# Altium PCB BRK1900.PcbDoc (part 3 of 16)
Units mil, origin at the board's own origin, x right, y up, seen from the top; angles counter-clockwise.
Board outline 8858.27 x 5905.51 mil, 10 copper layers (L1-TOP, L2-GND, L3-PWR, L4-GND, L5-PWR, L6-PWR, L7-GND, L8-SIG, L9-GND, L10-BOT), stack 48.824 mil thick; 456 components, 571 nets, 2296 pads, 2416 vias.
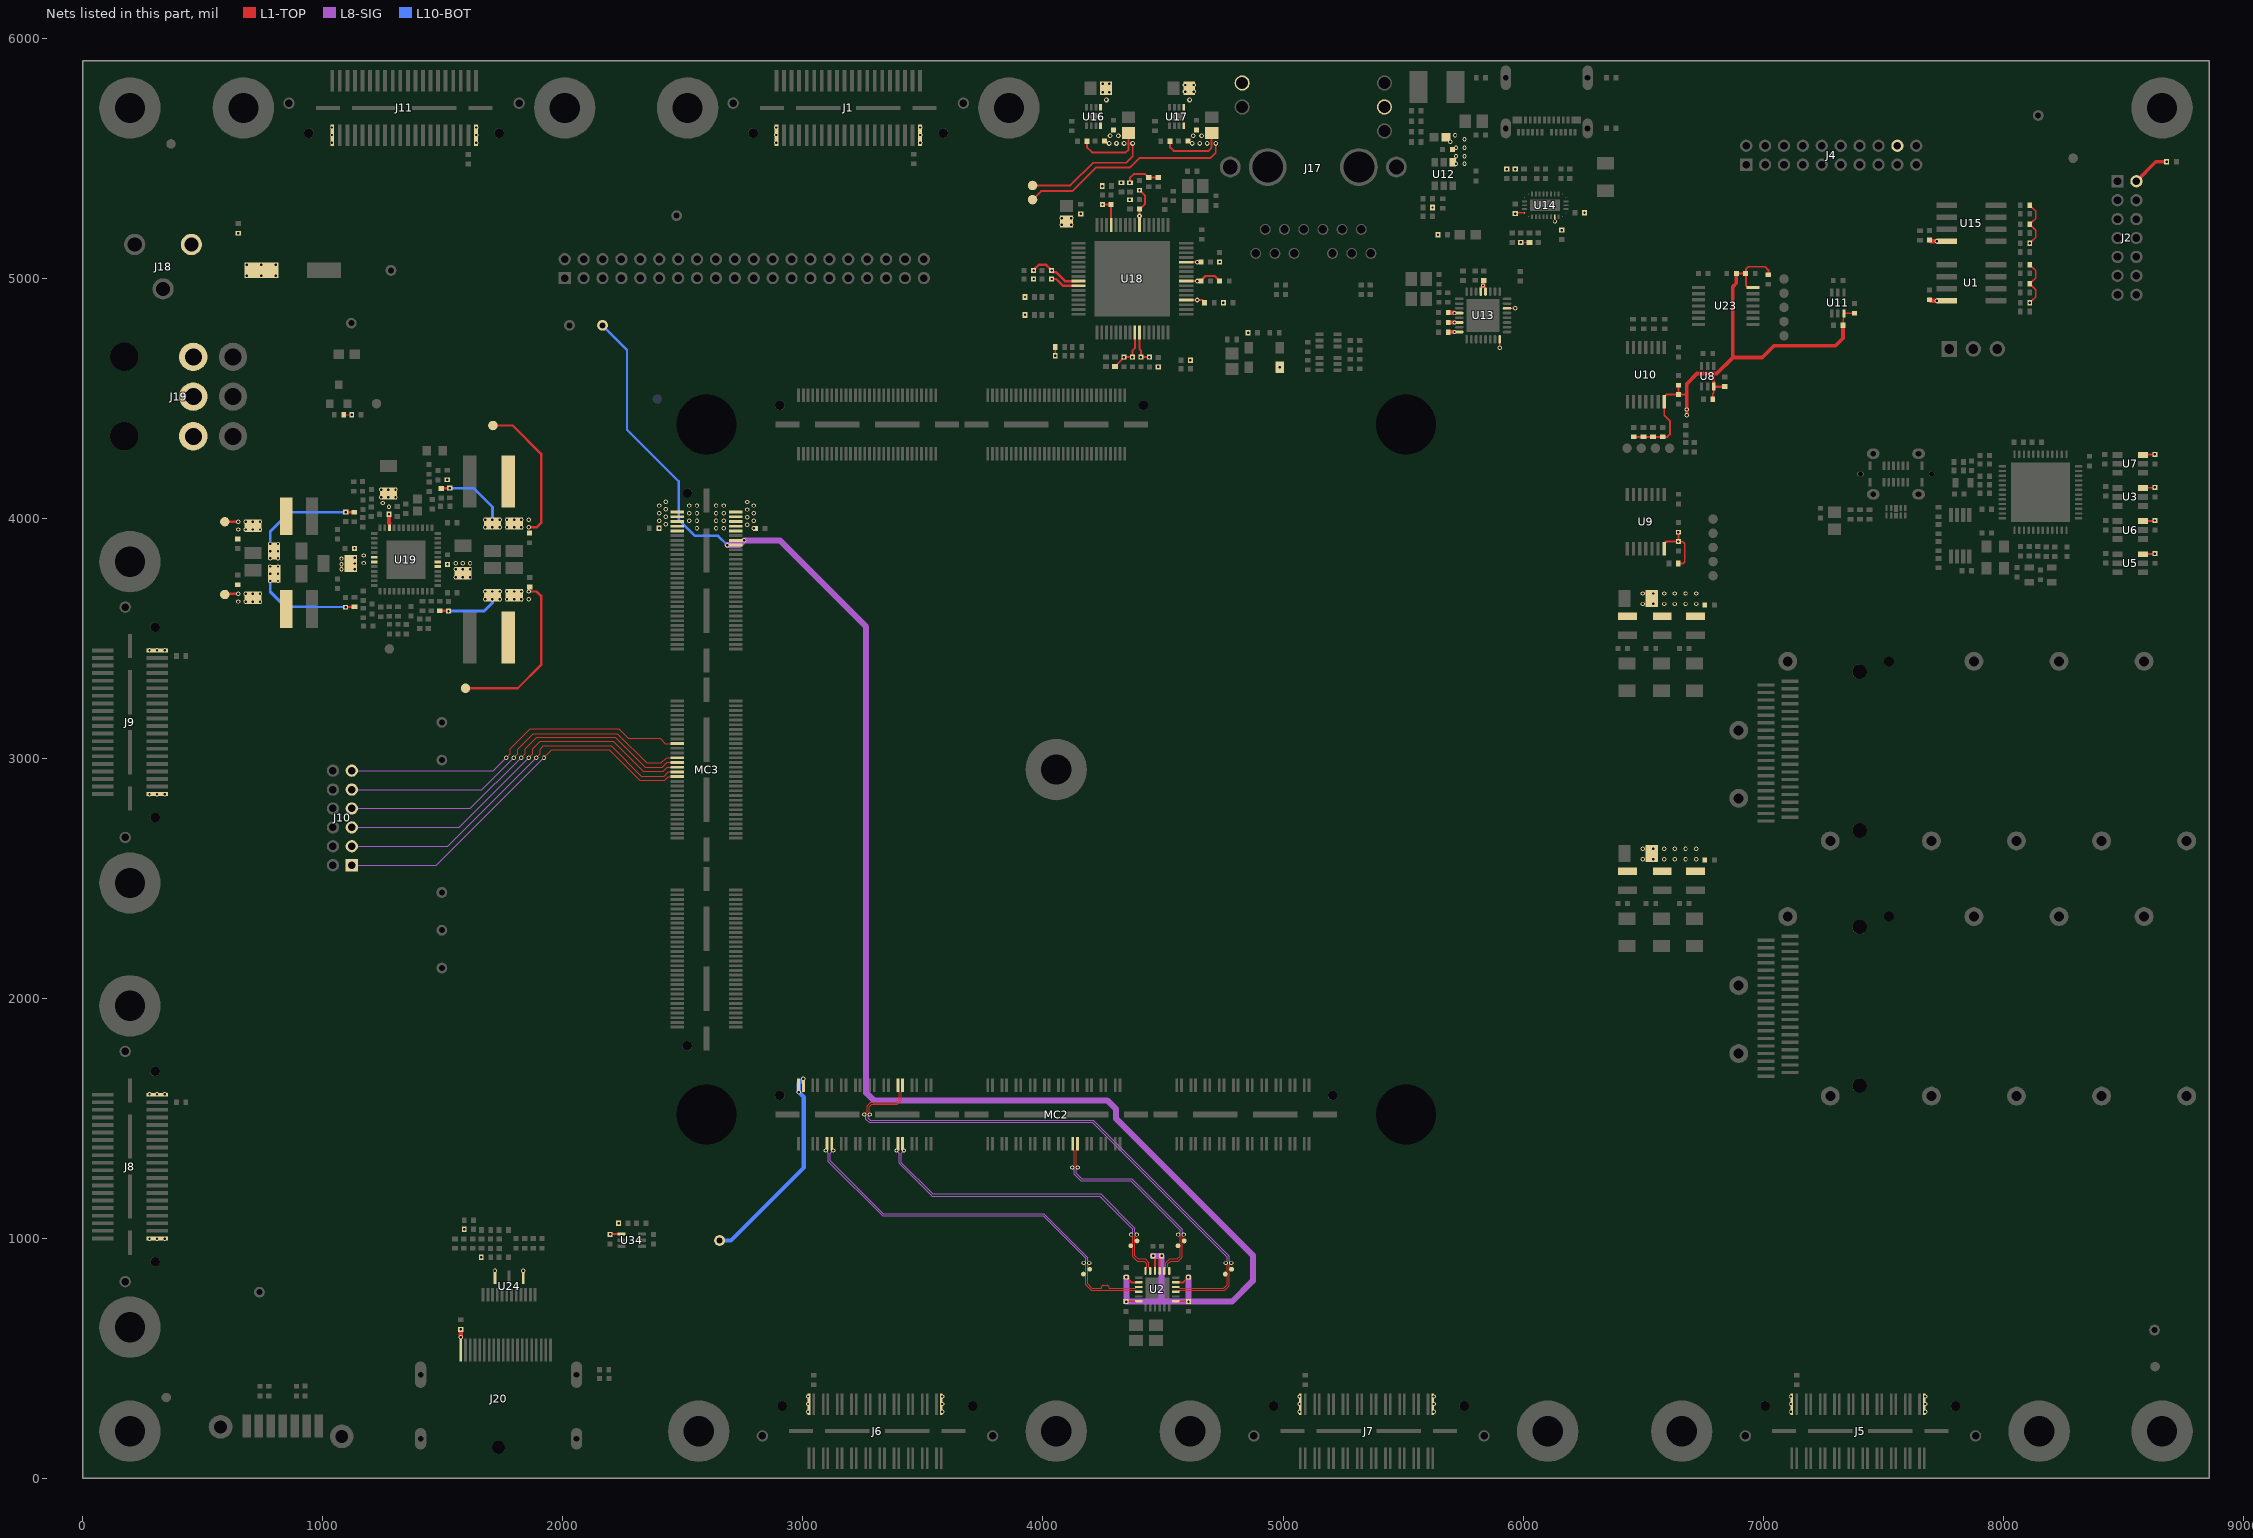
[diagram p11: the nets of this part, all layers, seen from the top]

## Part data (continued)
R2 R3 R4 R5 R6 R7 R68 R74 R80 R81 R83 R84 R85 R86 R87 R88 R89: library part 001521, "Thick-film resistor", Manufacturer=Vishay, ValueFloat=10000, x_tolerance=1
R8: library part 002203, "Thick-film resistor", Manufacturer=Yageo, Tolerance (%)=1, ValueFloat=14300
R9 R11 R21 R28 R103 R104 R106 R112 R120 R121 R140 R148: library part 001521, "Thick-film resistor", Manufacturer=Vishay, Tolerance (%)=1, ValueFloat=10000
R10: library part 001713, Manufacturer=Vishay, Manufacturer_PN=CRCW04020000Z0EDC, ValueFloat=0, x_tolerance=1
R12 R154 R159 R167: library part 001070, Manufacturer=Vishay, ValueFloat=100000, x_tolerance=1
R13 R19: library part 001919, "Thick-film resistor", Manufacturer=Vishay, Tolerance (%)=1, ValueFloat=5100
R14: library part 000934, Manufacturer=Vishay, ValueFloat=24900, x_tolerance=1
R15: library part 001783, Manufacturer=Vishay, ValueFloat=18700, x_tolerance=1
R16: library part 001549, "Thick-film resistor", Manufacturer=Vishay, ValueFloat=210000, x_tolerance=1
R17: library part 001550, "Thick-film resistor", Manufacturer=Vishay, ValueFloat=84500, x_tolerance=1
R18: library part 001035, Manufacturer=Vishay, ValueFloat=49900, x_tolerance=1
R20: library part 000826, "Thick-film resistor", Manufacturer=Vishay, Tolerance (%)=1, ValueFloat=12000
R22 R23 R24 R93 R108 R109 R110 R111: library part 000755, "Thick-film resistor", Manufacturer=Vishay, Tolerance (%)=1, ValueFloat=0
R25 R26: library part 001070, "Thick-film resistor", Manufacturer=Vishay, Tolerance (%)=1, ValueFloat=100000
R27 R138: library part 001162, "Thick-film resistor", Manufacturer=Vishay, Tolerance (%)=1, ValueFloat=2000
R41 R42 R43 R44 R45 R46 R47 R48 R49 R50 R51 R52 R97 R99 R100 R101: library part 001008, Manufacturer=Vishay, ValueFloat=4750, x_tolerance=1
R58: library part 000932, "Thick-film resistor", Manufacturer=Vishay, Tolerance (%)=1, ValueFloat=226000
R59: library part 001281, "Thick-film resistor", Manufacturer=Vishay, Tolerance (%)=1, ValueFloat=270000
R60 R134: library part 001618, "Thick-film resistor", Manufacturer=Vishay, Tolerance (%)=1, ValueFloat=374000
R61: library part 000967, "Thick-film resistor", Manufacturer=Vishay, Tolerance (%)=1, ValueFloat=118000
R62 R63 R64 R92: library part 002438, "NoLoad resistor", Manufacturer=Generic, Manufacturer_PN=Resistor-NoLoad
R65: library part 001162, Manufacturer=Vishay, ValueFloat=2000, x_tolerance=1
R66: library part 001121, Manufacturer=Vishay, ValueFloat=15000, x_tolerance=1
R67 R70 R73 R77 R78 R79 R119: library part 000755, "Thick-film resistor", Manufacturer=Vishay, ValueFloat=0, x_tolerance=1
R69: library part 000797, "Thick-film resistor", Manufacturer=Vishay, ValueFloat=1000, x_tolerance=1
R71: library part 001945, Manufacturer=Vishay, ValueFloat=499000, x_tolerance=1
R72: library part 001853, Manufacturer=Vishay, ValueFloat=887000, x_tolerance=1
R75 R117: library part 000800, "Thick-film resistor", Manufacturer=Vishay, ValueFloat=1000000, x_tolerance=5
R76: library part 001266, "Thick-film resistor", Manufacturer=Vishay, ValueFloat=8060, x_tolerance=1
R82: library part 001549, Manufacturer=Vishay, ValueFloat=210000, x_tolerance=1
R90 R91 R113 R114 R115 R116: library part 000801, "Thick-film resistor", Manufacturer=Vishay, Tolerance (%)=5, ValueFloat=2200
R94 R98 R102: library part 000760, "Thick-film resistor", Manufacturer=Vishay, ValueFloat=240, x_tolerance=1
R95: library part 002155, "Thick-film resistor", Manufacturer=Vishay, Tolerance (%)=1, ValueFloat=5760
R96 R105 R183 R184: library part 001388, "Thick-film resistor", Manufacturer=Vishay, Tolerance (%)=1, ValueFloat=2490
R107: library part 000800, "Thick-film resistor", Manufacturer=Vishay, Tolerance (%)=5, ValueFloat=1000000
R118: library part 001840, "Thick-film resistor", Manufacturer=Vishay, Tolerance (%)=1, ValueFloat=11000
R122 R125: library part 001091, Manufacturer=Vishay, Manufacturer_PN=CRCW040231K6FKED, ValueFloat=31600, x_tolerance=1
R123 R126 R130 R135: library part 001521, Manufacturer=Vishay, Manufacturer_PN=CRCW040210K0FKED, ValueFloat=10000, x_tolerance=1
R124 R127 R129 R133: library part 001121, "Thick-film resistor", Manufacturer=Vishay, Tolerance (%)=1, ValueFloat=15000
R128 R132: library part 001157, Manufacturer=Vishay, ValueFloat=52300, x_tolerance=1
R131: library part 001521, Manufacturer=Vishay, ValueFloat=10000, x_tolerance=1
R136: library part 000411, Manufacturer=Vishay, ValueFloat=0
R137: library part 000759, Manufacturer=Vishay, ValueFloat=10000, x_tolerance=5
R151 R152: library part 000755, Manufacturer=Vishay, ValueFloat=0, x_tolerance=1
R153 R158: library part 001715, Manufacturer=Vishay, ValueFloat=49.9, x_tolerance=1
R155 R156 R157: library part 001850, Manufacturer=Vishay, ValueFloat=1000000, x_tolerance=5
R168: library part 001388, Manufacturer=Vishay, ValueFloat=2490, x_tolerance=1
R169: library part 002012, Manufacturer=Vishay, ValueFloat=1500, x_tolerance=1
R181: library part 000969, Manufacturer=Vishay, ValueFloat=10, x_tolerance=1
TP1 TP2 TP3 TP4 TP5 TP6 TP7 TP8 TP9 TP10 TP11 TP12 TP13 TP14: library part TP-PTH-25/45, "Test point, plated through-hole, 25/45mil", partnumber=ALIGNI_IGNORE
TP15 TP16 TP17 TP18 TP22 TP23 TP32 TP33 TP34 TP35 TP36 TP37 TP38 TP39 TP40 TP41 TP42 TP43 TP44 TP45 TP46: library part TESTPOINT-SMD40, "Test point, surface-mount, 40mil"
TP19: "Test point, surface-mount, 40mil"
TP24 TP25 TP26 TP27 TP28 TP29 TP30 TP31: "Test point, surface-mount, 20mil", partnumber=ALIGNI_IGNORE
U1: library part 000842, "EEPROM", Manufacturer=Microchip
U2: library part 001741, Manufacturer="Silicon Labs"
U3 U5 U6 U7: library part 002400, "Level Translator, 0.65V - 3.6V, Direction Control", Manufacturer="Texas Instruments"
U4: library part 002398, Manufacturer=FTDI
U8 U11 U34: library part 002140, "Level Translator, 0.65V - 3.6V, Direction Control", Manufacturer="Texas Instruments"
U9 U10 U23: library part 000178, Manufacturer=Maxim
U12: library part 002224, "Load Switch with Adjustable Current Limit, Latching", Manufacturer="Diodes Incorporated"
U13: library part 001262, "Hi-Speed USB PHY with ULPI interface", Manufacturer=Microchip
U14: library part 001944, Manufacturer="Texas Instruments"
U15: library part 001296, "2 kb I2C EEPROM, 400 kHz", Manufacturer=Microchip
U16 U17: library part 002102, "LDO, 500 mA, 1.7-5.5V input, 0.6-5.3V output, 1% accuracy", Manufacturer=Maxim
U18: library part 002091, "Gigabit ethernet transceiver, RGMII", Manufacturer="Texas Instruments"
U19: library part 001511, Manufacturer="Texas Instruments"
U20: library part 002441, Manufacturer="Opal Kelly Incorporated"
U24: library part 001946, Manufacturer="Texas Instruments"
Y1: library part 001531, "Crystal", Manufacturer=Abracon
Y2: library part 001742, Manufacturer=Epson
Y3: library part 000770, "Crystal", Manufacturer="MMD Monitor / Quartztek"
Y4: library part 002402, "Crystal", Manufacturer=Abracon

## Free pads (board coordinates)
  round 18 hole 10 mask+2: ViaNoConnect1(1095,3628.92) ViaNoConnect1(1096.2,4025.16) ViaNoConnect1(1523.58,3612.56) ViaNoConnect1(1529,4125.08)

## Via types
v1: diameter 18, hole 10, L1-TOP to L10-BOT, tented both sides, 2170 vias
v2: diameter 20, hole 10, L1-TOP to L10-BOT, tented both sides, 246 vias

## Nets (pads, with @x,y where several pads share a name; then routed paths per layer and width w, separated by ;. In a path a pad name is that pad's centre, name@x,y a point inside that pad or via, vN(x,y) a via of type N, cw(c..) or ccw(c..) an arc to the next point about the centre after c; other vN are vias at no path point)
+1.1V_ETH: C83.2 C84.2 C85.2 C90.2 C91.2 C92.2 C93.2 C95.2 C96.2 C97.2 C98.2 R58.2 TP22.1 U16.8 U18.8 U18.29 U18.42 U18.58 | length 1330.2
  L1-TOP w8: TP22.1@3956.69,5385.83 4114.17,5385.83 4208.66,5480.31 4346.46,5480.31 4374.02,5507.87 4374.02,5560.48 v2(4373.26,5561.23) ; R58.2@4183.3,5570.09 4183.3,5544.5 4204.57,5523.23 4344.31,5523.23 4356.3,5535.22 C85.2@4356.3,5604.92 ; C95.2@4283.46,5306.69 4283.46,5222.29 U18.29@4284.06,5221.69 ; U18.58@4402.17,4772.87 4402.17,4703.97 4408.08,4698.07 C91.2@4408.08,4670.9 C90.2@4443.51,4670.9 ; U18.8@4597.06,4987.44 v2(4642.33,4987.44)
  L1-TOP w10: C93.2@4035.83,4995.47 v1(4035.83,4996.06) 4055.12,4996.06 4083.43,4967.75 U18.42@4148.24,4967.75 ; v2(4248.03,5306.69) C95.2@4283.46,5306.69 ; C98.2@4657.48,4988.19 4657.48,4988.78 4677.47,5008.77 4715.84,5008.77 4735.83,4988.78 C97.2@4735.83,4988.19
  other v1: 3961.02,4996.06
  other v2: 4408.08,4670.51 4443.51,4670.51 4275.59,5561.23 4306.33,5561.23 4337.83,5561.23 4279.53,5592.72 4314.21,5592.72
+1.8V: C1.2 C12.2 C30.2 C34.2 C40.2 C71.2 C72.2 C74.2 C99.2 C100.2 C101.2 C102.2 C105.2 C106.2 C109.2 C110.2 D2.2 J2.2 J4.18 MC2.1 MC2.3 R62.2 R63.2 R64.2 R68.2 R95.2 R97.1 R99.2 R100.2 R101.2 R104.2 R113.2 R114.2 R115.2 R116.2 R183.2 TP1.1 U3.6 U5.6 U6.6 U7.6 U13.8 U13.14 U13.28 U13.30 U13.32 U18.23 U18.41 U18.57 | length 2163.1
  L1-TOP w7: U13.8@5902.45,4745.06 5902.45,4709.84 v1(5903.02,4709.28) ; U13.14@5932.96,4873.99 5966.73,4873.99 v1(5967.02,4874.28)
  L1-TOP w8: v1(4051.18,4677.17) R64.2@4051.18,4712.6 ; R95.2@4299.83,4631.6 4301.8,4631.6 4307.64,4637.44 4307.64,4639.83 4330.39,4662.58 4330.39,4664.66 4336.62,4670.9 v2(4337.21,4670.9) v1(4372.65,4670.9) 4372.65,4698.07 4382.49,4707.91 U18.57@4382.49,4772.87 ; v1(4362.2,5397.64) 4362.2,5417.32 4377.95,5433.07 4425.2,5433.07 4438.98,5419.29 R115.2@4440.94,5419.29 R116.2@4480.31,5419.29 ; C109.2@4401.57,5365.75 v1(4402.17,5365.75) 4425.2,5342.72 4425.2,5310.04 4402.17,5287.01 C110.2@4401.57,5287.01 4401.86,5286.72 4401.86,5258.83 v2(4402.14,5258.55) U18.23@4402.17,5221.69 ; U5.6@8582.3,3850.02 8583.48,3851.2 8630.33,3851.2 v2(8631.51,3852.38) ; U6.6@8582.3,3987.81 8583.48,3988.99 8630.33,3988.99 v2(8631.51,3990.17) ; U3.6@8582.3,4125.61 8583.48,4126.79 8630.33,4126.79 v2(8631.51,4127.97) ; U7.6@8582.3,4263.4 8583.48,4264.58 8630.33,4264.58 v2(8631.51,4265.76)
  L1-TOP w10: v1(3961.02,5031.5) 3967.26,5037.73 3967.26,5039.85 3982.53,5055.12 4013.53,5055.12 4029.59,5039.06 4029.59,5037.73 v1(4035.83,5031.5) 4035.83,5030.91 4042.06,5024.67 4053.92,5024.67 4091.15,4987.44 U18.41@4148.24,4987.44
  L1-TOP w15: J2.2@8554.76,5403.22 8635.79,5484.25 v1(8680.71,5484.25)
  L1-TOP w18: C74.2@5688.09,4774.28 C74.2@5688.09,4774.28 5689.33,4775.57 v1(5714.14,4775.57) ; C72.2@5688.09,4815.28 5688.43,4814.94 v1(5714.14,4814.94) ; C71.2@5688.09,4856.28 5712.17,4856.28 v1(5714.14,4854.31)
  L1-TOP w25: C99.2@4095.7,5223.13 4098.43,5225.85 C99.2@4098.43,5235.24
  L10-BOT w18: TP1.1@2653,991 2700,991 3004,1295 3004,1587.68 v1(2982.28,1609.4) 2982.28,1645.72 v1(3001.97,1665.4)
  other v1: 4985.77,4628.25 4480.31,4629.92 4614.17,4657.48 4854.33,4771.65 3925.2,4846.46 3925.2,4921.26 4157.48,5267.32 5622.69,5294 4362.2,5326.77 4246.34,5383.29 4326.77,5397.64
  other v2: 4078.74,5222.44 4118.11,5222.44 4078.74,5250 4118.11,5250
+2.5V_ETH: C87.2 C88.2 C89.2 C103.2 C104.2 C107.2 C108.2 R60.2 TP46.1 U17.8 U18.4 U18.12 | length 1281.7
  L1-TOP w8: TP46.1@3956.69,5326.77 3992.13,5362.2 4122.05,5362.2 4220.35,5460.51 4362.08,5460.51 4401.57,5500 4696.85,5500 4719.72,5522.87 v2(4719.72,5561.23) ; R60.2@4529.53,5570.47 4529.53,5544.27 4543.91,5529.89 4689.58,5529.89 4702.76,5543.07 C89.2@4702.76,5604.92 ; U18.4@4597.06,4908.7 v2(4642.33,4908.7) ; U18.12@4597.06,5066.18 v2(4642.33,5066.18)
  L1-TOP w10: v2(4642.33,4908.7) 4662.17,4908.7 4667.4,4903.46 4667.99,4903.46 4673.23,4898.23 C103.2@4673.23,4897.64
  other v1: 4751.57,4897.64 4735.83,5066.93
  other v2: 4622.05,5561.23 4652.79,5561.23 4684.29,5561.23 4625.98,5592.72 4660.66,5592.72
+3.3V: C3.2 C4.2 C5.2 C6.2 C7.2 C8.2 MC3.166 MC3.168 TP3.1 U2.7 U2.11 U2.15 U2.16 U2.20 U2.24 | length 7320.6
  L1-TOP w8: C4.2@4346.46,736.61 4348.03,738.19 U2.24@4399.61,738.19 ; C3.2@4346.46,838.19 v1(4347.05,838.19) 4368.31,816.93 U2.20@4399.61,816.93 ; v1(4458.74,926.83) 4459.34,926.83 4466.54,919.63 U2.16@4466.54,864.17 ; U2.15@4486.22,864.17 4486.22,919.47 4493.59,926.83 v1(4494.18,926.83) ; U2.7@4553.15,738.19 4604.72,738.19 C8.2@4606.3,736.61 ; U2.11@4553.15,816.93 4584.45,816.93 v1(4605.71,838.19) C7.2@4606.3,838.19
  L8-SIG w25: v1(2685.08,3887.8) 2735.39,3887.8 v1(2755.08,3907.48) 2903.54,3907.48 3263.78,3547.24 3263.78,1606.3 3295.28,1574.8 4267.72,1574.8 4303.15,1539.37 4303.15,1500 4874.02,929.13 4874.02,822.83 4787.4,736.22 v1(4606.3,736.22) ; v1(4347.05,838.19) 4347.05,736.81 v1(4346.46,736.22) 4494.18,736.22 ; v1(4458.74,926.83) v1(4494.18,926.83) 4494.18,736.22 ; v1(4605.71,838.19) 4606.3,837.6 v1(4606.3,736.22) ; 4494.18,736.22 v1(4606.3,736.22)
  L10-BOT w10: TP3.1@2165.35,4803.15 2267.43,4701.07 2267.43,4368.57 2482.24,4153.76 2482.24,3993.76 2550,3926 2646.87,3926 v1(2685.08,3887.8) 2735.39,3887.8 v1(2755.08,3907.48)
+3.3V_AUX: C2.2 C73.2 C75.2 C82.2 C86.2 C94.2 C129.2 C130.2 C131.2 C133.2 C183.2 C218.2 J1.40 J5.40 J6.40 J7.40 J8.40 J9.40 J11.40 J17.14 J17.16 J20.20 L2.2 pad.ViaNoConnect1@1529,4125.08 R2.2 R3.2 R4.2 R65.2 R80.2 R82.2 R84.2 R85.2 R86.2 R125.2 R137.2 R138.2 R148.2 R151.1 R167.2 R168.2 TP16.1 U1.8 U13.20 U13.21 U14.8 U15.8 U16.1 U17.1 U24.13 U24.15 U34.1 | length 1695.3
  L1-TOP w5: R148.2@1087.69,4431 v1(1120.32,4431)
  L1-TOP w7: U14.8@6131.75,5256 6131.75,5236.75 v1(6132.55,5235.95) ; v1(8110.69,4897) 8110.69,4898.97 8117.03,4905.31 8119,4905.31 8134.97,4921.28 8134.97,4951.72 8119,4967.69 8117.03,4967.69 8110.69,4974.03 R3.2@8110.69,4976 8110.69,4977.97 8117.03,4984.31 8119,4984.31 8134.97,5000.28 8134.97,5031.72 8119,5047.69 8117.03,5047.69 8110.69,5054.03 R4.2@8110.69,5056 ; v1(8110.69,5145) 8110.69,5146.97 8117.03,5153.31 8119,5153.31 8134.97,5169.28 8134.97,5199.72 8119,5215.69 8117.03,5215.69 8110.69,5222.03 R85.2@8110.69,5224 8110.69,5225.97 8117.03,5232.31 8119,5232.31 8134.97,5248.28 8134.97,5279.72 8119,5295.69 8117.03,5295.69 8110.69,5302.03 R86.2@8110.69,5304
  L1-TOP w8: v1(2196.85,1016.54) 2197.64,1017.32 2243.31,1017.32 U34.1@2244.09,1018.11
  L1-TOP w9: C133.2@1528,4125.08 1527.3,4124.38 1494.7,4124.38 C133.2@1529,4125.08
  L1-TOP w10: TP16.1@1708.66,4385.83 1791.34,4385.83 1909.45,4267.72 1909.45,3980.32 1890.77,3961.64 v1(1857.58,3961.64) v1@1858.22,3961 ; U13.21@5823.71,4943.87 5823.9,4944.07 5823.9,4959.1 5833.02,4968.21 5843.2,4958.03 5843.2,4944.07 U13.20@5843.39,4943.87
  L1-TOP w12: v2(4276.81,5773.83) C82.2@4276.96,5773.83 ; C86.2@4592.13,5776.78 v2(4592.13,5776.93)
  L1-TOP w18: v1(1574.53,620.92) 1574.53,588.82 v1(1575.01,588.34) ; v1(5833.02,4969.28) 5834.19,4970.45 5834.19,4988.96 5835.43,4990.2 C73.2@5836.02,4990.2 ; C2.2@7693,4909.92 7693.59,4909.92 7697.51,4906 v1(7722.64,4906) U1.8@7764.64,4906 ; C94.2@7693,5157.92 7693.59,5157.92 7697.51,5154 v1(7722.64,5154) U15.8@7764.64,5154
  L10-BOT w12: pad.ViaNoConnect1@1529,4125.08 1629.32,4123.68 1706.58,4046.42 v1(1706.58,3993.81)
  other v1: 3580.33,278.35 5627.57,278.35 7674.82,278.35 3580.33,309.84 5627.57,309.84 7674.82,309.84 3580.33,341.34 5627.57,341.34 7674.82,341.34 1717.2,865.39 1835.31,865.39 1660.16,922 278.15,998.81 309.65,998.81 341.15,998.81 1588.84,1038 2232.28,1063.39 278.15,2849.21 309.65,2849.21 341.15,2849.21 1676.58,3961.64 1706.58,3961.64 1736.58,3961.64 1767.58,3961.64 1797.58,3961.64 1827.58,3961.64 1676.58,3993.81 1736.58,3993.81 1767.58,3993.81 1797.58,3993.81 1827.58,3993.81 1857.58,3993.81 1518,4160.32 5645.31,5180 6161.35,5200.08 6255.78,5272.32 5931.41,5454.01 1038.18,5564.37 2888.58,5564.37 1038.18,5595.86 2888.58,5595.86 1038.18,5627.36 2888.58,5627.36
  other v2: 4264.22,5742.32 4610.67,5742.32 4249.25,5773.83 4627.57,5776.93 4592.13,5804.49 4627.57,5804.49 4249.25,5809.26 4276.81,5809.26
+3.3V_QSFP: C50.2 C51.2 C52.2 C60.2 C61.2 C63.2 C64.2 C66.2 C67.2 C68.2 C119.2 C120.2 C121.2 C122.2 C212.2 C213.2 L1.2 L5.1 L6.1 L7.1 L8.1 L9.1 L10.1 pad.ViaNoConnect1@1523.58,3612.56 R41.2 R42.2 R43.2 R44.2 R45.2 R46.2 R51.2 R52.2 R122.2 TP15.1 U8.6 U9.14 U10.14 U11.6 U23.14 | length 3428.4
  L1-TOP w6: R41.2@6790.37,4495.95 6790.37,4518.43 6794.49,4522.54 U8.6@6794.49,4547.65 ; R51.2@7332.5,4803.67 7332.5,4828.14 7336.61,4832.26 U11.6@7336.61,4853.36
  L1-TOP w8: R46.2@6461.28,4338.68 R45.2@6501.28,4338.68 R44.2@6541.28,4338.68 R43.2@6581.28,4338.68 6601.28,4338.68 6611.28,4348.68 6611.28,4405.36 6588.05,4428.59 U10.14@6588.05,4484.81 ; U10.14@6587.43,4484.18 6587.43,4504.85 6596.91,4514.34 6646.59,4514.34 C64.2@6646.59,4552.92 ; U9.14@6587.78,3872.61 6587.78,3893.28 6597.27,3902.76 v1(6646.94,3902.76) ; R42.2@6646.65,3811.02 6665.35,3811.02 6673.23,3818.9 6673.23,3893.7 6665.35,3901.57 6648.13,3901.57 v1(6646.94,3902.76) ; v1(6646.94,3941.35) v1(6646.94,3902.76) ; C63.2@6647.22,4514.97 6681.1,4514.97 ; C213.2@6889.01,5019.06 C212.2@6927.59,5019.06 ; U23.14@6937.08,4959.89 6927.59,4969.38 C212.2@6927.59,5019.06 ; R52.2@7021.65,5013.78 7021.65,5033.46 7007.87,5047.24 6937.01,5047.24 6927.59,5037.83 C212.2@6927.59,5019.06 ; U11.6@7336.61,4853.36 7336.84,4853.59 C66.2@7380.02,4853.59
  L1-TOP w10: TP15.1@1594.49,3291.34 1812.23,3291.34 1909.45,3388.56 1909.45,3675.96 1890.77,3694.64 v1(1857.58,3694.64) v1@1858.22,3695.28 ; 6795.28,4602.36 6794.49,4601.57 U8.6@6794.49,4547.65 6794.72,4547.87 C50.2@6839.9,4547.87
  L1-TOP w11: R122.2@1487.58,3613.95 1522.19,3613.95 C122.2@1523.58,3612.56
  L1-TOP w15: v1(6681.1,4429.13) v1(6681.1,4452.76) 6681.1,4514.97 6681.1,4559.06 6724.41,4602.36 6795.28,4602.36 6807.09,4602.36 6874.02,4669.29 ; C213.2@6888.38,5019.68 6888.38,4978.93 6874.02,4964.57 6874.02,4669.29 ; R51.2@7332.5,4803.67 7332.5,4749.82 7300.91,4718.23 7045,4718.23 6996.06,4669.29 6874.02,4669.29
  L10-BOT w12: pad.ViaNoConnect1@1523.58,3612.56 1671.56,3612.56 1706.58,3647.58 v1(1706.58,3662.46)
  other v1: 6498.03,2579.72 6542.72,2579.72 6587.4,2579.72 6632.09,2579.72 6676.77,2579.72 6721.46,2579.72 6498.03,2623.03 6542.72,2623.03 6587.4,2623.03 6632.09,2623.03 6676.77,2623.03 6721.46,2623.03 6498.03,3642.72 6542.72,3642.72 6587.4,3642.72 6632.09,3642.72 6676.77,3642.72 6721.46,3642.72 1676.58,3662.46 1736.58,3662.46 1767.58,3662.46 1797.58,3662.46 1827.58,3662.46 1857.58,3662.46 6498.03,3686.02 6542.72,3686.02 6587.4,3686.02 6632.09,3686.02 6676.77,3686.02 6721.46,3686.02 1676.58,3694.64 1706.58,3694.64 1736.58,3694.64 1767.58,3694.64 1797.58,3694.64 1827.58,3694.64
+5V_AUX: C69.2 C76.2 C142.2 C143.2 C144.2 C145.2 C220.2 L3.2 pad.ViaNoConnect1@1096.2,4025.16 R71.2 R74.2 R81.2 R128.2 TP17.1 U12.1 U14.30 | length 602.2
  L1-TOP w5: v1(5990.41,5148.64) R74.2@6026.41,5148.64
  L1-TOP w7.5: v1(5967.41,5268.24) 5970.91,5271.75 U14.30@6005.76,5271.75
  L1-TOP w10: TP17.1@592,3985 648.39,3985 v1(648.58,3984.81) ; C145.2@1095.8,4025.55 pad.ViaNoConnect1@1096.2,4025.16 ; pad.ViaNoConnect1@1096.2,4025.16 1130.8,4025.16 pad.ViaNoConnect1@1096.2,4025.16
  L10-BOT w12: v1(781.19,3892.58) 781.19,3944.19 861.76,4024.76 pad.ViaNoConnect1@1096.2,4025.16
  other v1: 781.19,3832.58 813.36,3832.58 781.19,3862.58 813.36,3862.58 813.36,3892.58 648.58,3952.64 678.58,3952.64 708.58,3952.64 738.58,3952.64 678.58,3984.81 708.58,3984.81 738.58,3984.81 5967.41,5454.01 5720.47,5476.38 5755.91,5476.38 5720.47,5507.87 5755.91,5507.87 5720.47,5543.31 5755.91,5543.31 5696.85,5567.91 5755.91,5578.74 5716.54,5594.49
+5V_SZG: C150.2 C151.2 C152.2 C153.2 J1.2 J5.2 J6.2 J7.2 J8.2 J9.2 J11.2 L4.2 pad.ViaNoConnect1@1095,3628.92 R132.2 TP18.1 | length 521
  L1-TOP w10: TP18.1@585,3682 587.64,3684.64 v1(648.58,3684.64) ; C153.2@1095,3628.92 1130.8,3630.12 1096.2,3630.12 C153.2@1095,3628.92
  L10-BOT w12: v1(781.35,3738.42) 781.35,3693.65 843.69,3631.32 pad.ViaNoConnect1@1095,3628.92
  other v1: 3021.15,278.35 5068.39,278.35 7115.64,278.35 3021.15,309.84 5068.39,309.84 7115.64,309.84 3021.15,341.34 5068.39,341.34 7115.64,341.34 278.15,1599.71 309.65,1599.71 341.15,1599.71 278.15,3450.11 309.65,3450.11 341.15,3450.11 648.58,3652.46 678.58,3652.46 708.58,3652.46 738.58,3652.46 678.58,3684.64 708.58,3684.64 738.58,3684.64 813.53,3738.42 781.35,3768.42 813.53,3768.42 781.35,3798.42 813.53,3798.42 1639.08,5564.37 3489.48,5564.37 1639.08,5595.86 3489.48,5595.86 1639.08,5627.36 3489.48,5627.36
+VDCIN: C20.1 C21.1 C116.1 C117.1 C127.1 C128.1 C134.1 C135.2 C140.1 C141.1 J18.1 J19.1 J19.2 J19.3 MC3.171 MC3.172 MC3.173 MC3.174 MC3.175 MC3.176 MC3.177 MC3.178 MC3.179 MC3.180 U19.5 U19.6 U19.22 U19.30 U19.31 | length 38
  L1-TOP w18: v1(1276.08,4016) 1276.08,3980.14 1277.58,3978.64
  other v1: 1553.58,3754.46 1583.58,3754.46 1613.58,3754.46 1078.11,3786.64 1133.86,3787.4 1553.58,3786.64 1583.58,3786.64 1613.58,3786.64 1519.58,3807.56 1078.11,3808.64 1133.86,3811.02 1553.58,3811.7 1583.58,3811.7 1613.58,3811.7 1170.95,3812.84 1078.11,3831.64 1133.86,3834.65 1170.95,3844.33 1132.08,3874 2401.01,3957.97 2558.49,3957.97 2638.36,3957.97 2669.86,3957.97 2795.84,3957.97 2768.28,3972.73 2428.15,3974.41 2401.01,3989.46 2526.99,3989.46 2558.49,3989.46 2638.36,3989.46 2669.86,3989.46 2795.84,3989.46 2768.28,4004.23 2428.15,4005.91 2401.01,4020.96 2526.99,4020.96 2558.49,4020.96 2638.36,4020.96 2669.86,4020.96 2795.84,4020.96 2768.28,4035.72 2428.15,4037.4 1276,4047 2401.01,4052.46 2526.99,4052.46 2558.49,4052.46 2638.36,4052.46 2669.86,4052.46 2795.84,4052.46 1250,4063 2768.28,4067.22 2428.15,4068.9 1243,4086.83 1273,4086.83 1303,4086.83 1243,4119 1273,4119 1303,4119 684.09,5010 744.09,5010 804.09,5010 684.09,5056 744.09,5056 804.09,5056 648,5186.92
B68_L2N_N3: J10.7 MC3.93 | length 1549.3
  L1-TOP w4: v1(1826.77,3002.58) 1843.27,3019.08 1843.27,3038.62 1891.26,3086.61 2218.36,3086.61 2342.36,2962.61 2415.07,2962.61 2434.75,2982.28 MC3.93@2476.77,2982.28
  L8-SIG w4: J10.7@1121,2790.74 1614.93,2790.74 v1(1826.77,3002.58)
B68_L2P_N2: J10.5 MC3.91 | length 1575.9
  L1-TOP w4: v1(1858.27,3002.58) 1874.76,3019.08 1874.76,3039.58 1906.05,3070.87 2209.04,3070.87 2335.02,2944.88 2418.09,2944.88 2435.81,2962.6 MC3.91@2476.77,2962.6
  L8-SIG w4: J10.5@1121,2712 1567.68,2712 v1(1858.27,3002.58)
B68_L18N_N11: J10.3 MC3.89 | length 1599.5
  L1-TOP w4: v1(1889.76,3002.58) 1906.26,3019.08 1906.26,3038.07 1919.37,3051.18 2200.88,3051.18 2326.87,2925.2 2421.54,2925.2 2439.25,2942.91 MC3.89@2476.77,2942.91
  L8-SIG w4: J10.3@1121,2633.26 1520.44,2633.26 v1(1889.76,3002.58)
B68_L18P_N10: J10.1 MC3.87 | length 1613.2
  L1-TOP w4: v1(1921.26,3002.58) 1953.5,3034.83 2193.52,3034.83 2319.92,2908.43 2424.17,2908.43 2438.98,2923.23 MC3.87@2476.77,2923.23
  L8-SIG w4: J10.1@1121,2554.52 1473.19,2554.52 v1(1921.26,3002.58)
B68_T0U_N12: J10.9 MC3.95 | length 1522.2
  L1-TOP w4: v1(1795.28,3002.58) 1811.77,3019.08 1811.77,3036.93 1877.2,3102.36 2227.65,3102.36 2349.7,2980.32 2410.84,2980.32 2432.49,3001.97 MC3.95@2476.77,3001.97
  L8-SIG w4: J10.9@1121,2869.48 1662.17,2869.48 v1(1795.28,3002.58)
B68_T2U_N12: J10.11 MC3.101 | length 1464.4
  L1-TOP w4: v1(1763.78,3002.58) 1780.28,3019.08 1780.28,3038.45 1863.87,3122.05 2232.28,3122.05 2271.65,3082.68 2405.51,3082.68 2427.17,3061.02 MC3.101@2476.77,3061.02
  L8-SIG w4: J10.11@1121,2948.22 1709.42,2948.22 v1(1763.78,3002.58)
CLK0A: MC2.10 TP28.1 U2.22 | length 1640
  L1-TOP w3.3: v1(4170.17,897.64) 4170.17,895.35 4177.17,888.35 4177.17,806.17 4200.43,782.9 4383.58,782.9 4388.92,777.56 U2.22@4399.61,777.56
  L8-SIG w3.15: v1(3094.49,1366.09) 3105.74,1354.85 3105.74,1319.46 3331.83,1093.36 4000.21,1093.36 4177.17,916.41 4177.17,906.91 4170.17,899.91 v1(4170.17,897.64)
CLK0B: MC2.12 TP24.1 U2.21 | length 1640
  L1-TOP w3.3: v1(4193.17,897.64) 4193.17,895.35 4186.17,888.35 4186.17,809.9 4204.16,791.9 4220.47,791.9 4239.22,791.9 ccw(c4239.22,797.56) 4244.88,797.56 4244.88,798.56 cw(c4250.54,798.56) 4250.54,804.22 4267.52,804.22 cw(c4267.52,798.56) 4273.18,798.56 4273.18,797.56 ccw(c4278.84,797.56) 4278.84,791.9 4308.79,791.9 4383.58,791.9 4388.92,797.24 U2.21@4399.61,797.24
  L8-SIG w3.15: v1(3125.98,1366.09) 3114.74,1354.85 3114.74,1323.19 3335.56,1102.36 4003.94,1102.36 4186.17,920.13 4186.17,906.91 4193.17,899.91 v1(4193.17,897.64)
CLK1A: MC2.30 TP29.1 U2.18 | length 1368.1
  L1-TOP w3.3: v1(4367.02,1015.75) 4367.02,1013.46 4374.02,1006.46 4374.02,924.28 4392.78,905.51 4421.26,905.51 4432.51,894.26 4432.51,880.2 4427.17,874.86 U2.18@4427.17,864.17
  L8-SIG w3.15: v1(3389.76,1366.09) 3401.01,1354.85 3401.01,1312.26 3534.6,1178.68 3537.23,1176.04 4236.43,1176.04 4374.02,1038.45 4374.02,1025.02 4367.02,1018.02 v1(4367.02,1015.75)
CLK1B: MC2.32 TP25.1 U2.17 | length 1368.1
  L1-TOP w3.3: v1(4390.02,1015.75) 4390.02,1013.46 4383.02,1006.46 4383.02,928.01 4396.51,914.51 4424.99,914.51 4441.51,897.99 4441.51,880.2 4446.85,874.86 U2.17@4446.85,864.17
  L8-SIG w3.15: v1(3421.26,1366.09) 3410.01,1354.85 3410.01,1315.99 3540.96,1185.04 4240.16,1185.04 4383.02,1042.18 4383.02,1025.02 4390.02,1018.02 v1(4390.02,1015.75)
CLK2A: MC2.66 TP30.1 U2.14 | length 894.4
  L1-TOP w3.3: v1(4122.36,1295.28) 4122.36,1297.56 4129.36,1304.56 4129.36,1365.79 4124.02,1371.13 MC2.66@4124.02,1394.09 ; U2.14@4505.91,864.17 4505.91,874.86 4511.25,880.2 4511.25,897.43 4528.33,914.51 4560.18,914.51 4570.87,925.2 4570.87,1006.46 4563.87,1013.46 v1(4563.87,1015.75)
  L8-SIG w3.15: v1(4122.36,1295.28) 4122.36,1293.01 4129.36,1286.01 4129.36,1267.36 4157.69,1239.03 4366.35,1239.03 4570.87,1034.52 4570.87,1025.02 4563.87,1018.02 v1(4563.87,1015.75)
CLK2B: MC2.68 TP26.1 U2.13 | length 894.4
  L1-TOP w3.3: MC2.68@4143.7,1394.09 4143.7,1371.53 4138.36,1366.19 4138.36,1304.56 4145.36,1297.56 v1(4145.36,1295.28) ; U2.13@4525.59,864.17 4525.59,874.86 4520.25,880.2 4520.25,893.7 4532.06,905.51 4563.91,905.51 4579.87,921.47 4579.87,1006.46 4586.87,1013.46 v1(4586.87,1015.75)
  L8-SIG w3.15: v1(4145.36,1295.28) 4145.36,1293.01 4138.36,1286.01 4138.36,1271.09 4161.42,1248.03 4370.08,1248.03 4579.87,1038.24 4579.87,1025.02 4586.87,1018.02 v1(4586.87,1015.75)
CLK3A: MC2.29 TP31.1 U2.10 | length 2355.7
  L1-TOP w3.3: v1(3255.19,1515.94) 3255.19,1518.22 3267.29,1530.32 3267.29,1551.67 3282.55,1566.93 3389.76,1566.93 3401.01,1578.18 3401.01,1609.42 3395.67,1614.76 MC2.29@3395.67,1637.4 ; U2.10@4553.15,797.24 4563.84,797.24 4569.18,791.9 4752.53,791.9 4767.72,807.09 4767.72,888.35 4760.72,895.35 v1(4760.72,897.64)
  L8-SIG w3.15: v1(3255.19,1515.94) 3255.19,1513.67 3262.19,1506.67 3262.19,1497.19 3276.26,1483.13 4205.85,1483.13 4725.92,963.06 4732.28,956.69 4767.72,921.26 4767.72,906.91 4760.72,899.91 v1(4760.72,897.64)
CLK3B: MC2.31 TP27.1 U2.9 | length 2366.3
  L1-TOP w3.3: v1(3278.19,1515.94) 3276.29,1517.85 3276.29,1547.94 3286.28,1557.93 3393.49,1557.93 3410.01,1574.45 3410.01,1609.42 3415.35,1614.76 MC2.31@3415.35,1637.4 ; U2.9@4553.15,777.56 4563.84,777.56 4569.18,782.9 4756.26,782.9 4776.72,803.36 4776.72,888.35 4783.72,895.35 v1(4783.72,897.64)
  L8-SIG w3.15: v1(3278.19,1515.94) 3278.19,1513.67 3271.19,1506.67 3271.19,1500.92 3279.98,1492.13 4209.58,1492.13 4738.65,963.06 4776.72,924.99 4776.72,906.91 4783.72,899.91 v1(4783.72,897.64)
